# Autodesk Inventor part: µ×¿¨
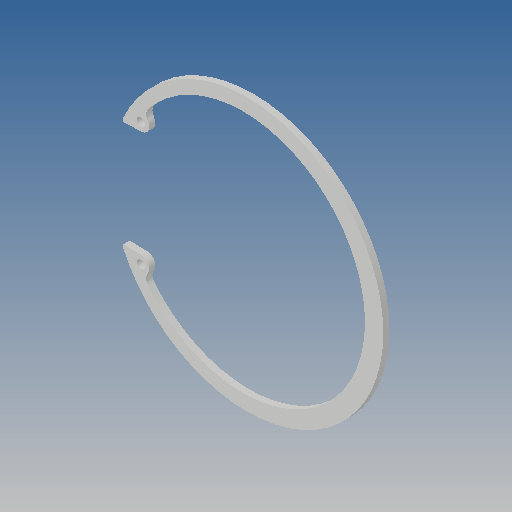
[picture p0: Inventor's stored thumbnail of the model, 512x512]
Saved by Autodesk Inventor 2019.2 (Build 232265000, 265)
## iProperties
Created: 2013-07
Part Number: µ×¿¨
Material: Ogólny
Document SubType Name: Modeling
Designer: CADENGINEERING4
Density: 1 g/cm^3
Appearance: Domyślna
Author: CADENGINEERING4
Revision Number: ÈÎºÎ
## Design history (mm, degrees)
feature "Í¹Ì¨-À­Éì1"
node "Bryła1"
